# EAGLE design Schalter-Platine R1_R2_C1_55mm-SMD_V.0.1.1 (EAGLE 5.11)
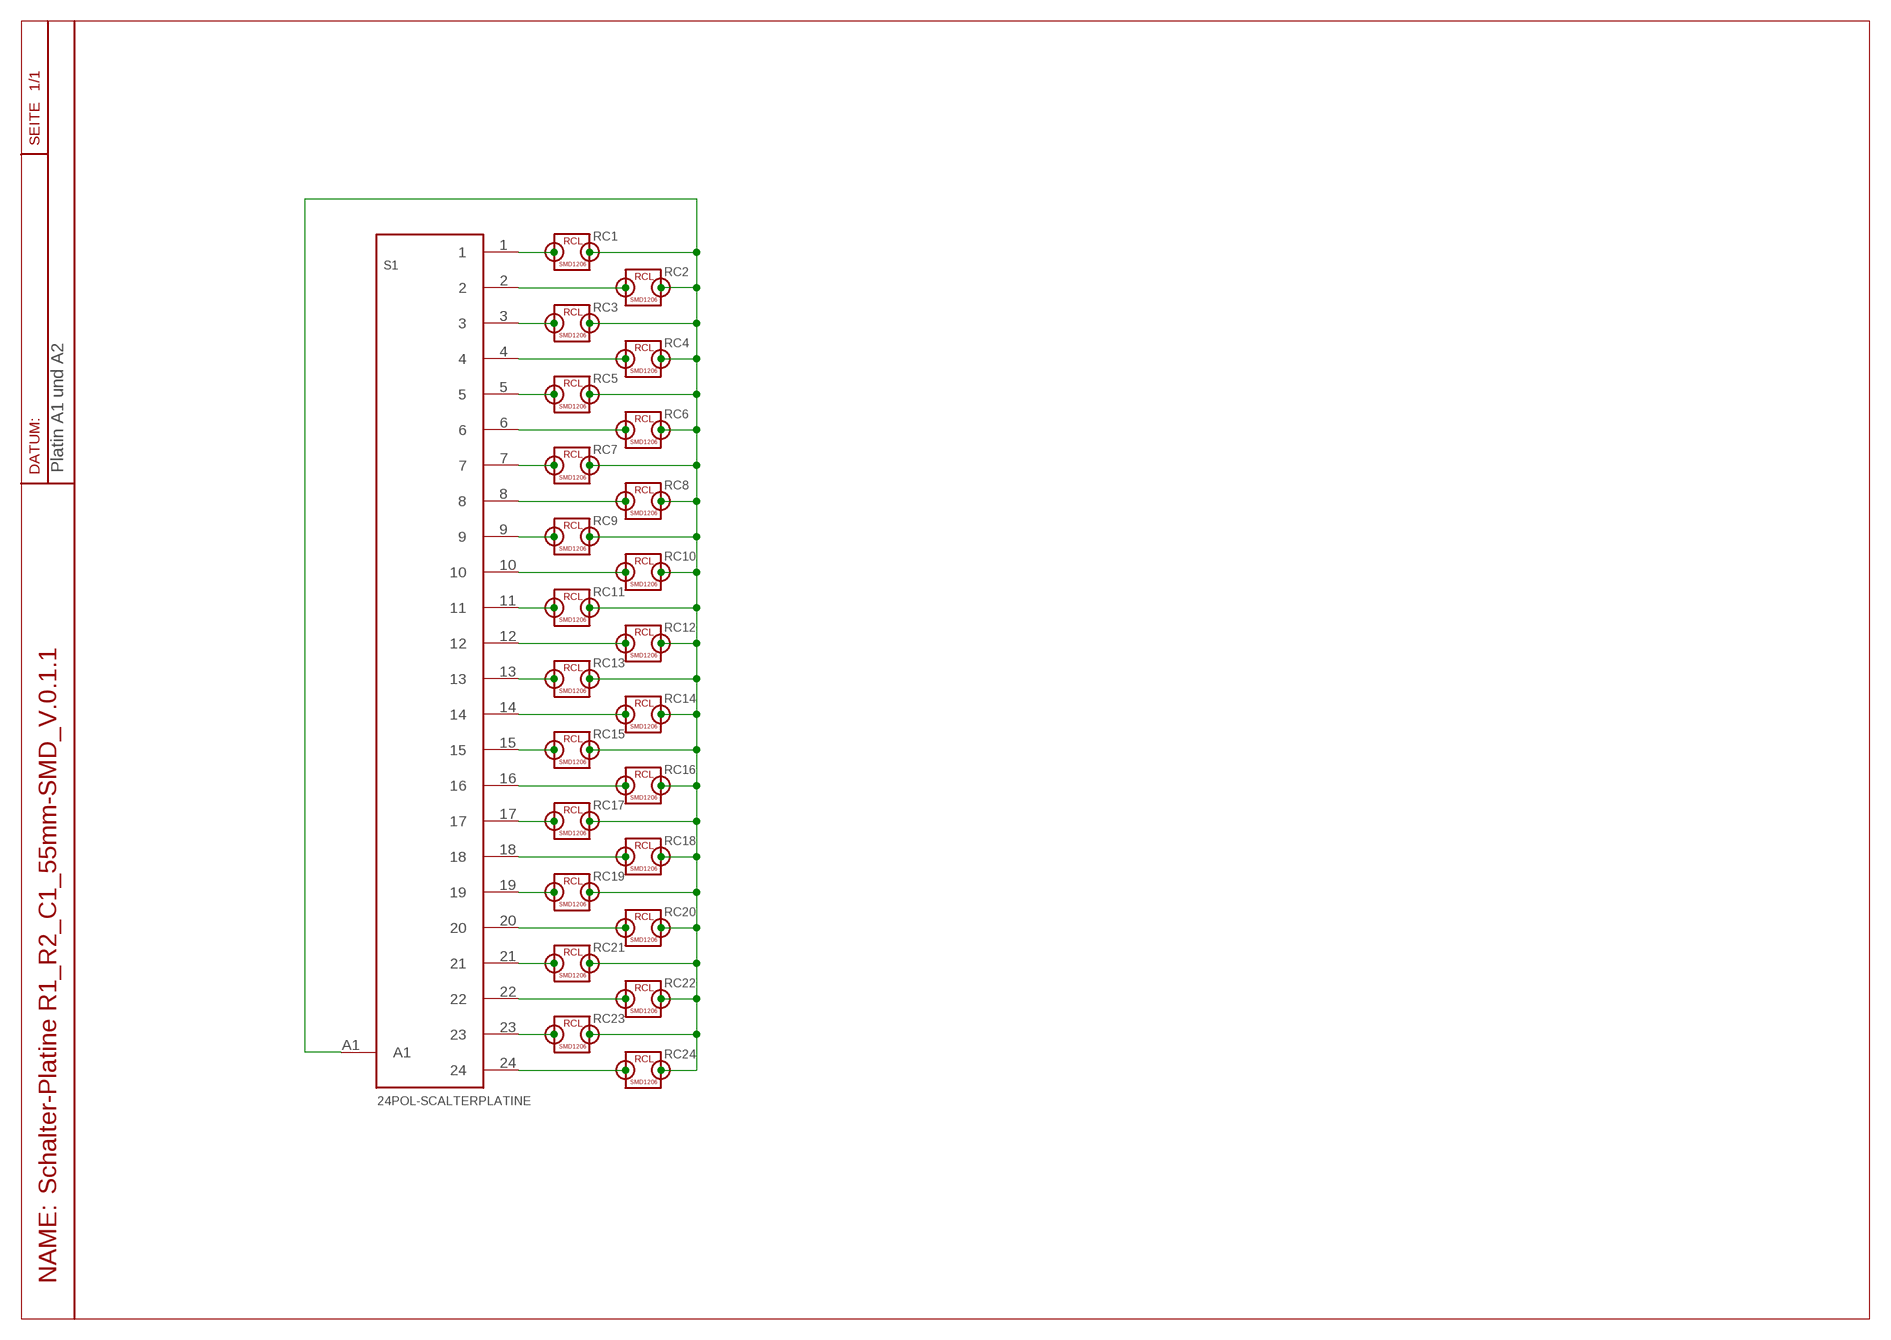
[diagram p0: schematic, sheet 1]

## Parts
RC1  RCL-L-KURZ  [PUNKTE-KURZ]
RC2  RCL-L-KURZ  [PUNKTE-KURZ]
RC3  RCL-L-KURZ  [PUNKTE-KURZ]
RC4  RCL-L-KURZ  [PUNKTE-KURZ]
RC5  RCL-L-KURZ  [PUNKTE-KURZ]
RC6  RCL-L-KURZ  [PUNKTE-KURZ]
RC7  RCL-L-KURZ  [PUNKTE-KURZ]
RC8  RCL-L-KURZ  [PUNKTE-KURZ]
RC9  RCL-L-KURZ  [PUNKTE-KURZ]
RC10  RCL-L-KURZ  [PUNKTE-KURZ]
RC11  RCL-L-KURZ  [PUNKTE-KURZ]
RC12  RCL-L-KURZ  [PUNKTE-KURZ]
RC13  RCL-L-KURZ  [PUNKTE-KURZ]
RC14  RCL-L-KURZ  [PUNKTE-KURZ]
RC15  RCL-L-KURZ  [PUNKTE-KURZ]
RC16  RCL-L-KURZ  [PUNKTE-KURZ]
RC17  RCL-L-KURZ  [PUNKTE-KURZ]
RC18  RCL-L-KURZ  [PUNKTE-KURZ]
RC19  RCL-L-KURZ  [PUNKTE-KURZ]
RC20  RCL-L-KURZ  [PUNKTE-KURZ]
RC21  RCL-L-KURZ  [PUNKTE-KURZ]
RC22  RCL-L-KURZ  [PUNKTE-KURZ]
RC23  RCL-L-KURZ  [PUNKTE-KURZ]
RC24  RCL-L-KURZ  [PUNKTE-KURZ]
S1  24POL-SCALTERPLATINE  24POL-SCALTERPLATINEKLEIN  [DREHSCHALTERPLATINE]

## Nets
N$1: RC1.2 RC2.2 RC3.2 RC4.2 RC5.2 RC6.2 RC7.2 RC8.2 RC9.2 RC10.2 RC11.2 RC12.2 RC13.2 RC14.2 RC15.2 RC16.2 RC17.2 RC18.2 RC19.2 RC20.2 RC21.2 RC22.2 RC23.2 RC24.2 S1.A1
N$2: RC1.1(1A) S1.1
N$3: RC2.1(1A) S1.2
N$4: RC3.1(1A) S1.3
N$5: RC4.1(1A) S1.4
N$6: RC5.1(1A) S1.5
N$7: RC6.1(1A) S1.6
N$8: RC7.1(1A) S1.7
N$9: RC8.1(1A) S1.8
N$10: RC9.1(1A) S1.9
N$11: RC10.1(1A) S1.10
N$12: RC11.1(1A) S1.11
N$13: RC12.1(1A) S1.12
N$14: RC13.1(1A) S1.13
N$15: RC14.1(1A) S1.14
N$16: RC15.1(1A) S1.15
N$17: RC16.1(1A) S1.16
N$18: RC17.1(1A) S1.17
N$19: RC18.1(1A) S1.18
N$20: RC19.1(1A) S1.19
N$21: RC20.1(1A) S1.20
N$22: RC21.1(1A) S1.21
N$23: RC22.1(1A) S1.22
N$24: RC23.1(1A) S1.23
N$25: RC24.1(1A) S1.24
Unconnected: RC1.1U RC1.2U RC2.1U RC2.2U RC3.1U RC3.2U RC4.1U RC4.2U RC5.1U RC5.2U RC6.1U RC6.2U RC7.1U RC7.2U RC8.1U RC8.2U RC9.1U RC9.2U RC10.1U RC10.2U RC11.1U RC11.2U RC12.1U RC12.2U RC13.1U RC13.2U RC14.1U RC14.2U RC15.1U RC15.2U RC16.1U RC16.2U RC17.1U RC17.2U RC18.1U RC18.2U RC19.1U RC19.2U RC20.1U RC20.2U RC21.1U RC21.2U RC22.1U RC22.2U RC23.1U RC23.2U RC24.1U RC24.2U

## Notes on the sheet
- Platin A1 und A2

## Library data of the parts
RC1-RC24 = RLC-BOX:RCL-L-KURZ
S1 = RLC-BOX:24POL-SCALTERPLATINE

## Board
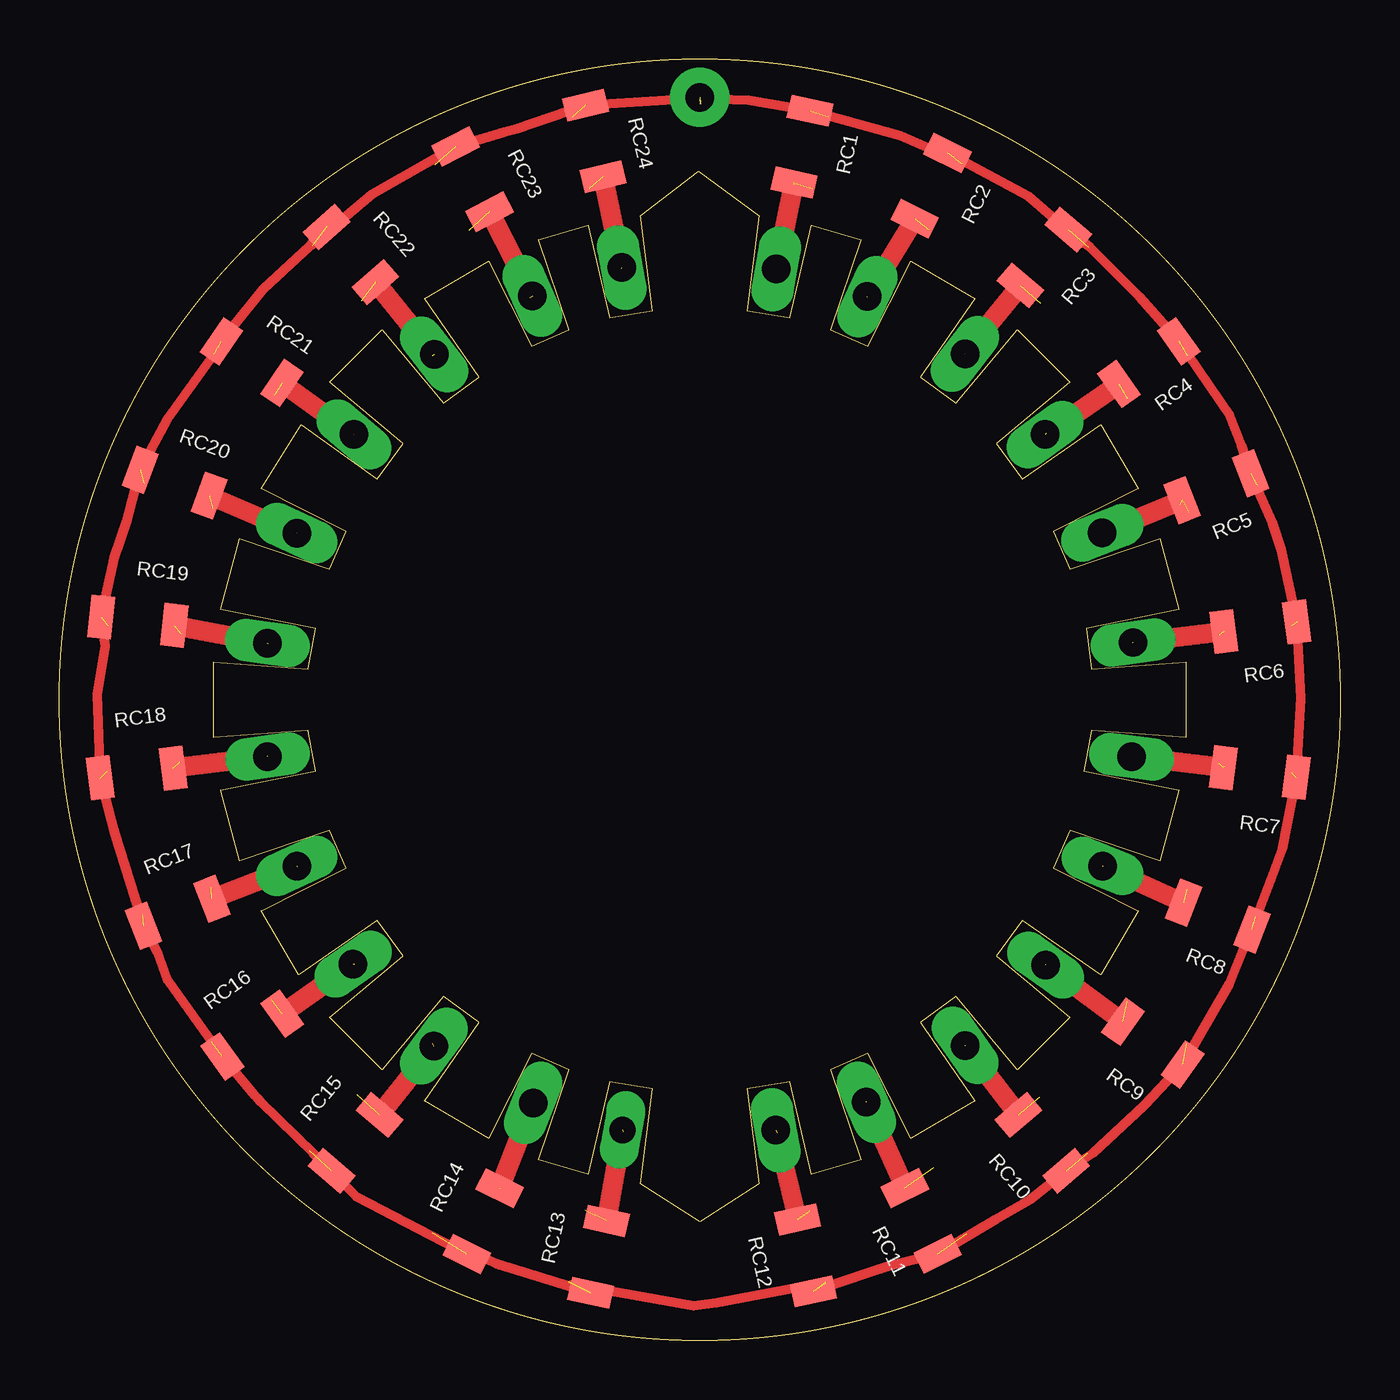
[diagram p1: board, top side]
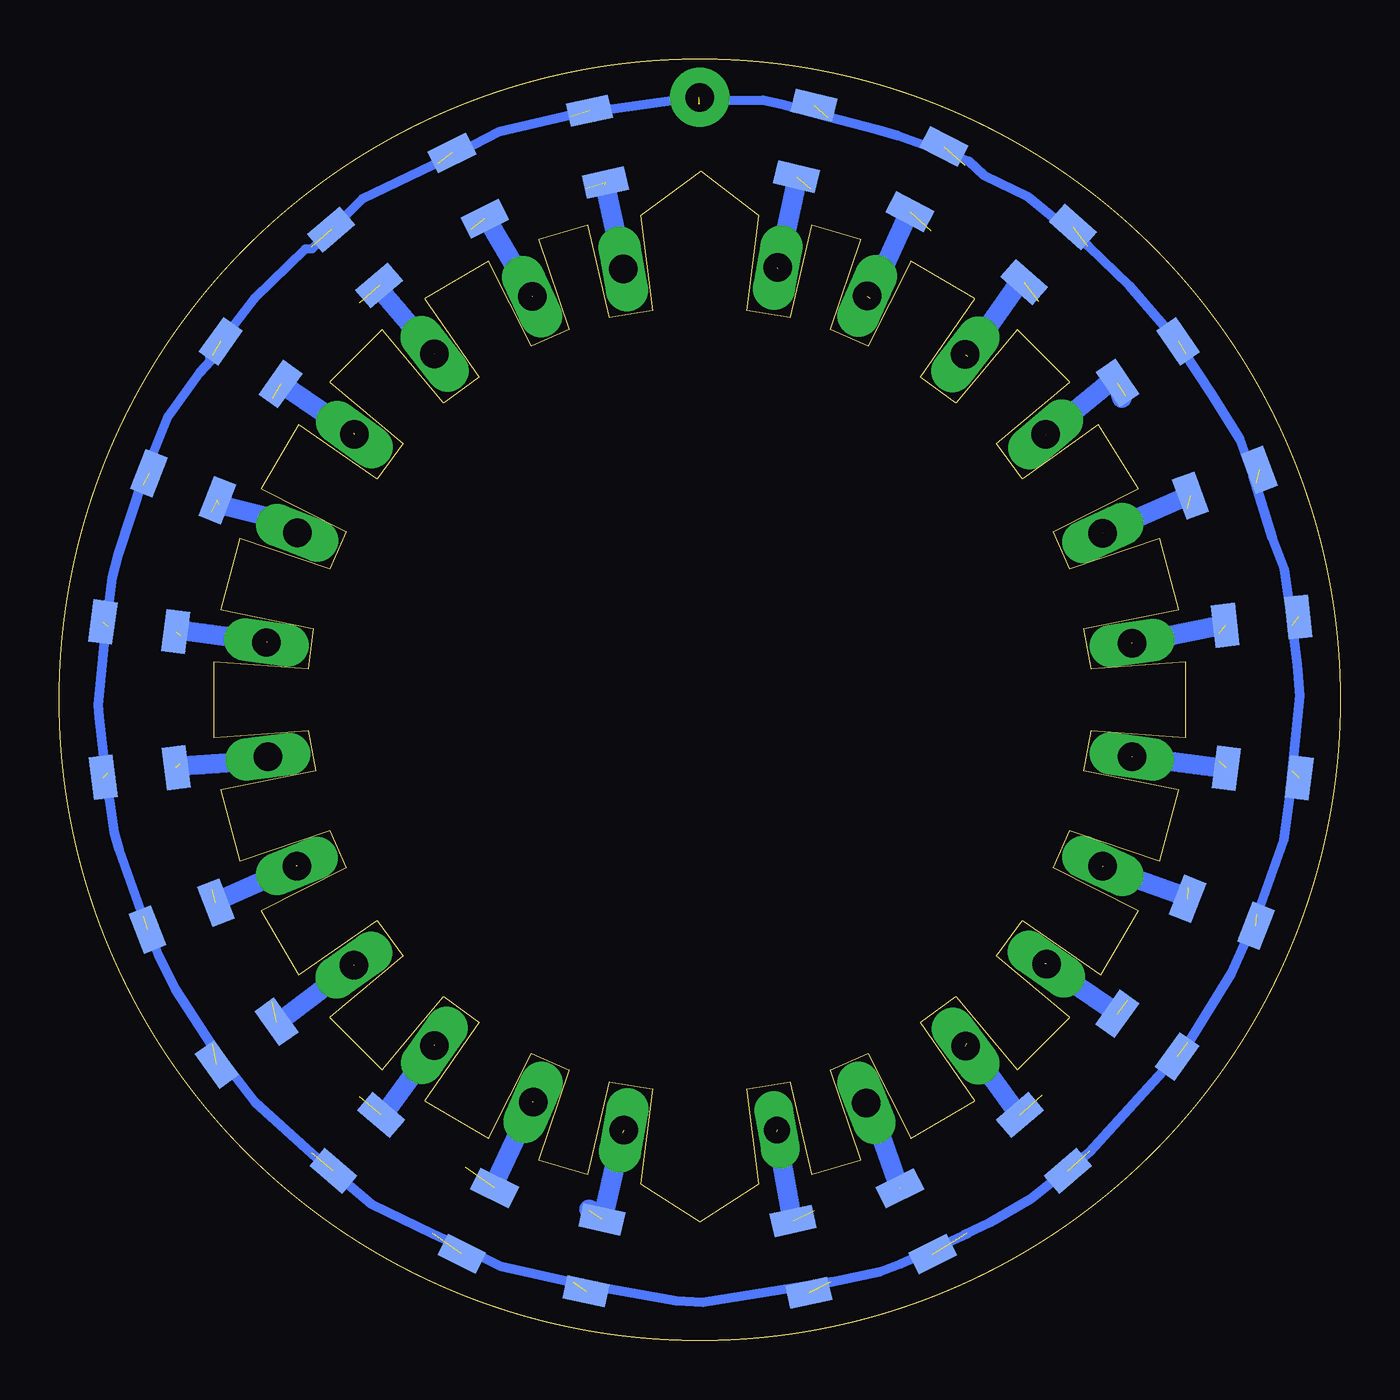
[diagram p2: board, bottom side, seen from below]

Size 54 x 54 mm. Coordinates in mm from the lower left corner, seen from the top.
Outline: circle at 27,27 radius 27
Copper layers (1*16): Top 0.035mm / dielectric 1.5mm / Bottom 0.035mm
Design rules "PCBWay": minimum track width 8mil, minimum drill 0.3mm, track to track 6mil, track to pad 6mil, pad to pad 6mil, via to via 6mil, smd to smd 6mil, copper to edge 40mil, drill to drill 8mil, minimum pad ring 10mil, minimum via ring 8mil, stop-mask expansion 4mil, vias tented up to drill 0mil, thermal gap 20mil

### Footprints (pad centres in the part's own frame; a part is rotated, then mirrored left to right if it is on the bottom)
PUNKTE-KURZ = smd 1 x 1.8: 1 1.55,0; 2 -1.55,0 | smd 1 x 1.8 bottom: 1U 1.55,0; 2U -1.55,0
DREHSCHALTERPLATINE = drill 1.2 pad 1.6 long: 1 3.228,18.163; 2 7.064,16.998; 3 11.181,14.582; 4 14.562,11.184; 5 16.972,7.033; 6 18.265,2.413; 7 18.212,-2.398; 8 16.982,-7.008; 9 14.582,-11.189; 10 11.189,-14.575; 11 7.026,-16.97; 12 3.208,-18.151; 14 -7.025,-16.995; 15 -11.209,-14.607; 16 -14.62,-11.143; 17 -16.99,-7.01; 18 -18.219,-2.395; 19 -18.23,2.39; 20 -16.99,7.023; 21 -14.585,11.181; 22 -11.196,14.554; 23 -7.056,17.026; 24 -3.282,18.225 | drill 1.1 pad 1.6 long: 13 -3.256,-18.141 | drill 1.2 pad 2.5 round: A1 0,25.4

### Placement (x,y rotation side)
RC1  31.31,50.32 257.5 top
RC2  36.75,48.67 243.5 top
RC3  41.53,45.64 229.5 top
RC4  45.93,41.21 215.5 top
RC5  48.78,35.98 201.5 top
RC6  50.62,30.08 187.5 top
RC7  50.61,23.93 172.5 top
RC8  48.84,17.88 158.5 top
RC9  46.1,12.53 144.5 top
RC10  41.44,8.32 130.5 top
RC11  36.34,5.03 116.5 top
RC12  31.46,3.58 102.5 top
RC13  22.73,3.51 77.5 top
RC14  17.87,5.02 63.5 top
RC15  12.49,8.32 49.5 top
RC16  8.14,12.86 35.5 top
RC17  4.99,18.04 21.5 top
RC18  3.26,23.91 7.5 top
RC19  3.31,30.31 353.5 top
RC20  4.86,36.15 339.5 top
RC21  8.11,41.23 325.5 top
RC22  12.3,45.77 311.5 top
RC23  17.42,48.95 297.5 top
RC24  22.55,50.56 283.5 top
S1  27,27 0 top

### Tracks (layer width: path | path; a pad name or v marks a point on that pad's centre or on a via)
N$1  (30 unrouted)
  Top 0.406: RC13.2 18.43,3.22 16.97,3.91 RC14.2 12.54,6.04 10.7,7.89 RC15.2 8.48,10.05 8.35,10.21 8.24,10.32 6.76,12.09 RC16.2 4.54,15.21 4.15,16.32 RC17.2 2.39,21.17 2.3,21.53 RC18.2 1.6,27.23 1.94,29.27 RC19.2 2.32,33 2.84,34.54 RC20.2 4.57,38.86 6.47,41.48 RC21.2 8.6,44.32 10.55,46.12 RC22.2 10.63,46.17 13.19,48.31 RC23.2 18.76,50.92 19.3,51.07 RC24.2 25.92,52.29 27.01,52.34 S1.A1 27,52.34 29.06,52.28 RC1.2 35.45,50.77 36.8,50.19 RC2.2 40.85,48.24 43.12,46.26 RC3.2 43.44,46.09 45.54,43.99 RC4.2 49.32,39.03 49.82,37.75 RC5.2 51.13,34.47 51.52,33.32 RC6.2 52.29,27.89 52.34,27.06 RC7.2 51.55,20.7 51.07,19.4 RC8.2 49.95,16.54 49.32,15.02 RC9.2 45.73,9.87 43.59,7.9 RC10.2 40.91,5.92 39.48,5.1 RC11.2 35,3.14 34.15,2.86 RC12.2 | 21.63,2.36 26.74,1.46 27.7,1.58 32.31,2.44
  Bottom 0.406: 21.49,2.44 19.41,2.88 18.52,3.22 15.72,4.5 | 15.82,4.47 14.75,4.98 13.05,5.97 10.57,7.93 6.43,12.5 4.6,15.46 4.07,16.65 3.48,18.01 2.38,21.1 2.16,22.63 1.7,27.15 1.8,28.48 2.03,30.33 2.35,32.5 2.87,33.82 3.68,36.47 4.22,37.99 5.44,39.91 6.61,41.7 6.91,42.16 8.88,44.45 10.61,46.12 13.16,48.21 14.99,49.09 15.65,49.7 18.65,50.78 19.52,51.04 21.61,51.59 23.56,52.1 24.34,52.27 27.03,52.26 | 27,52.33 27.9,52.29 32.38,51.67 35.46,50.95 37.07,50.11 38.26,49.54 41.22,48.13 43.34,46.01 43.64,45.99 45.77,43.94 47.66,41.47 47.62,41.31 48.08,40.79 49.44,38.91 50.15,37.14 50.45,36.39 51.52,33.13 51.76,32.15 52.06,29.79 52.37,26.77 52.31,26.26 52.07,24.04 51.68,21.41 51.48,20.67 50.44,17.76 49.83,16.26 49.11,14.8 47.55,12.4 47.25,11.96 45.75,10.02 43.36,7.87 43.14,7.69 40.83,5.73 38.25,4.5 36.67,3.75 35.4,3.12 32.38,2.44 28,1.66 26.86,1.6 21.46,2.46
N$2  (2 unrouted)
  Top 0.813: S1.1 RC1.1
  Bottom 0.813: S1.1 31,48.71
N$3  (2 unrouted)
  Top 0.813: S1.2 RC2.1
  Bottom 0.813: 34.04,43.99 35.9,47.15
N$4  (2 unrouted)
  Top 0.813: S1.3 RC3.1
  Bottom 0.813: 38.18,41.6 40.5,44.32
N$5  (2 unrouted)
  Top 0.813: S1.4 RC4.1
  Bottom 0.813: 41.59,38.23 44.62,40.3
N$6  (2 unrouted)
  Top 0.813: S1.5 RC5.1
  Bottom 0.813: 43.61,34.33 47.25,35.22
N$7  (2 unrouted)
  Top 0.813: S1.6 RC6.1
  Bottom 0.813: 45.23,29.43 49.11,29.96
N$8  (2 unrouted)
  Top 0.813: S1.7 RC7.1
  Bottom 0.813: 45.41,24.44 49.11,24.18
N$9  (2 unrouted)
  Top 0.813: RC8.1 S1.8
  Bottom 0.813: 47.35,18.51 44.01,20
N$10  (2 unrouted)
  Top 0.813: RC9.1 S1.9
  Bottom 0.813: S1.9 44.79,13.39
N$11  (2 unrouted)
  Top 0.813: RC10.1 S1.10
  Bottom 0.813: 38.21,12.43 40.33,9.5
N$12  (2 unrouted)
  Top 0.813: RC11.1 S1.11
  Bottom 0.813: 35.76,6.39 34.03,10.07
N$13  (2 unrouted)
  Top 0.813: RC12.1 S1.12
  Bottom 0.813: 30.26,8.75 31.05,5.27 31.67,5.52
N$14  (2 unrouted)
  Top 0.813: RC13.1 S1.13
  Bottom 0.813: 23.12,5.15 23.77,8.78
N$15  (1 unrouted)
  Top 0.813: RC14.1 S1.14
  Bottom 0.813: 18.59,6.41 19.89,10.11
N$16  (2 unrouted)
  Top 0.813: RC15.1 S1.15
  Bottom 0.813: 13.74,9.76 15.75,12.5
N$17  (2 unrouted)
  Top 0.813: RC16.1 S1.16
  Bottom 0.813: 9.42,13.79 12.46,15.86
N$18  (2 unrouted)
  Top 0.813: RC17.1 S1.17
  Bottom 0.813: 6.42,18.67 10.02,19.96
N$19  (2 unrouted)
  Top 0.813: RC18.1 S1.18
  Bottom 0.813: 4.87,24.11 8.75,24.61
N$20  (2 unrouted)
  Top 0.813: RC19.1 S1.19
  Bottom 0.813: 5.07,30.12 8.8,29.37
N$21  (2 unrouted)
  Top 0.813: RC20.1 S1.20
  Bottom 0.813: 6.6,35.52 10.01,34.03
N$22  (2 unrouted)
  Top 0.813: RC21.1 S1.21
  Bottom 0.813: S1.21 9.48,40.59 9.2,39.71
N$23  (2 unrouted)
  Top 0.813: RC22.1 S1.22
  Bottom 0.813: 15.72,41.48 13.65,44.42
N$24  (2 unrouted)
  Top 0.813: RC23.1 S1.23
  Bottom 0.813: 18.2,47.5 19.83,43.92
N$25  (2 unrouted)
  Top 0.813: S1.24 RC24.1
  Bottom 0.813: 23.7,45.17 22.88,48.99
